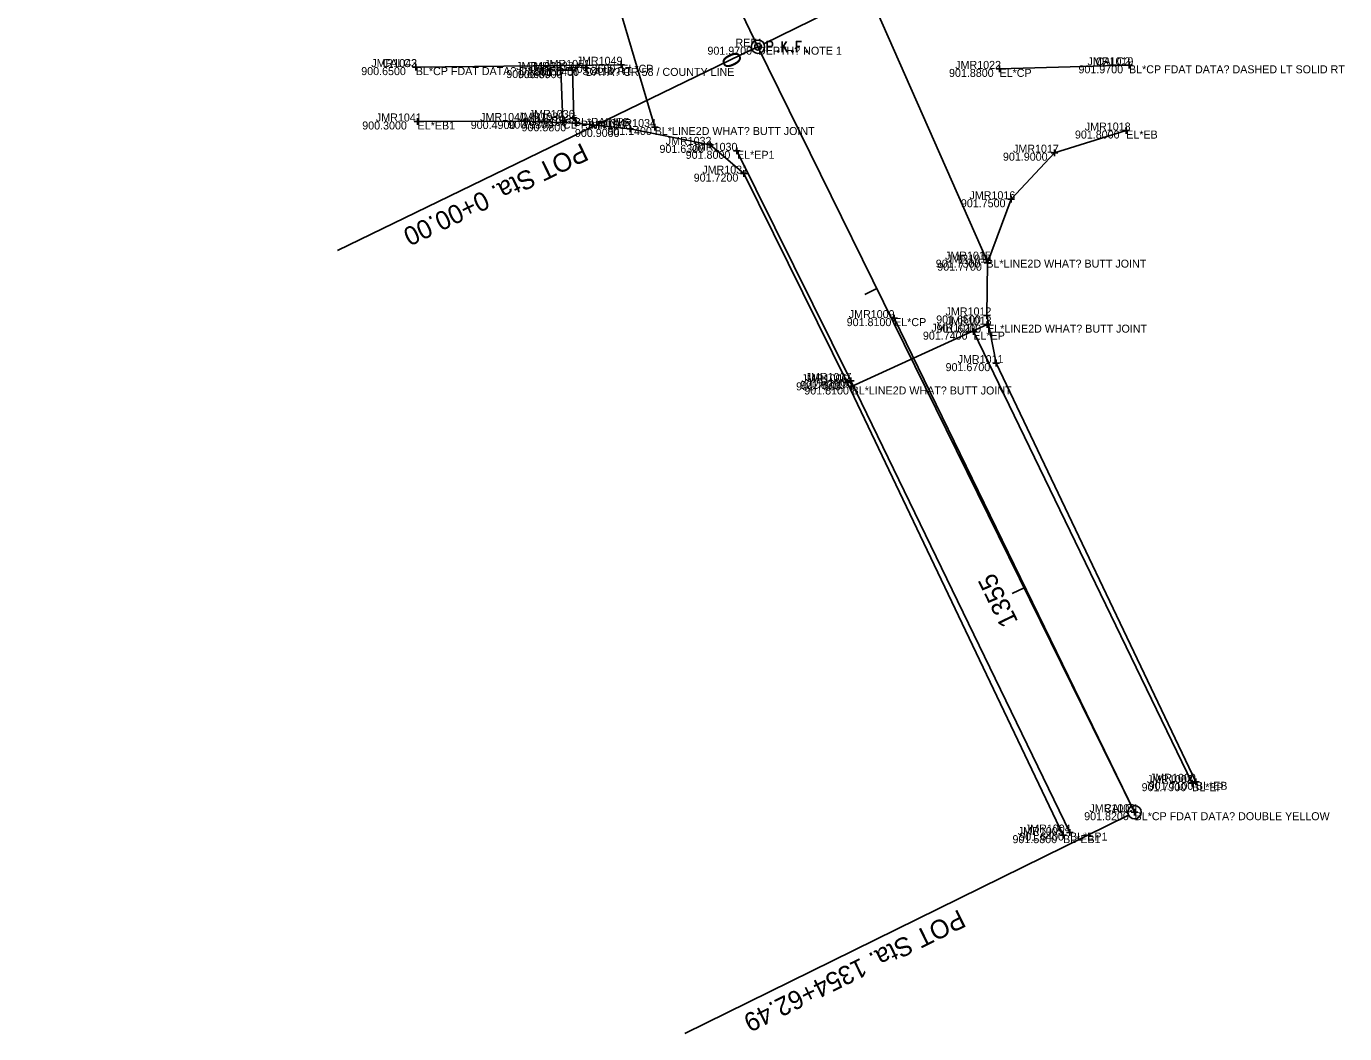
# Model space of a CAD drawing. Extents: x 1800057 to 1804439, y 483822 to 495007.
# Drawn here: x 1804241.5 to 1804439.2, y 483821.7 to 483972.7 of the extents above; entities that cross this region are included whole.
import ezdxf

# ---------------------------------------------------------------- set-up
doc = ezdxf.new("R2010")
doc.units = 0
for name, color, linetype in [('Default', 7, 'Continuous'), ('PM_X_Stop_Line', 7, 'Continuous'), ('PV_X_EOP', 7, 'Continuous'), ('PV_X_Shoulder', 7, 'Continuous'), ('SV_X_Center_of_Pavt', 7, 'Continuous'), ('SV_X_CL_Survey_20', 7, 'Continuous'), ('SV_X_Control_Cells_Found', 7, 'Continuous'), ('SV_X_Shot_Marker', 7, 'Continuous'), ('SV_X_Text_Comment', 7, 'Continuous'), ('SV_X_Text_Elevation', 7, 'Continuous'), ('SV_X_Text_Name', 7, 'Continuous')]:
    doc.layers.add(name, color=color, linetype=linetype)

msp = doc.modelspace()

# ---------------------------------------------------------------- linework, layer by layer
at = {"layer": 'Default'}
for p, q in [((1804335.76, 483957.63), (1804326.1, 483990.39)), ((1804385.49, 483937.75), (1804367.66, 483978.25)), ((1804365.29, 483918.73), (1804385.6, 483928))]:
    msp.add_line(p, q, dxfattribs=at)
at = {"layer": 'PM_X_Stop_Line'}
msp.add_lwpolyline([(1804323.65, 483958.99), (1804323.43, 483966.15), (1804321.7, 483966.17), (1804322, 483958.59), (1804323.65, 483958.99)], dxfattribs=at)
at = {"layer": 'PV_X_EOP'}
msp.add_line((1804416.35, 483859.26), (1804383.54, 483926.95), dxfattribs=at)
msp.add_lwpolyline([(1804398.03, 483851.86), (1804365.17, 483919.56), (1804348.1, 483954.06)], dxfattribs=at)
at = {"layer": 'PV_X_Shoulder'}
for points in [[(1804396.99, 483851.47), (1804364.63, 483919.35), (1804349.15, 483950.64), (1804344.09, 483954.95), (1804332.09, 483957.34), (1804323.97, 483958.19), (1804316.38, 483958.53), (1804300.21, 483958.46)], [(1804416.91, 483859.47), (1804386.95, 483922.23), (1804385.56, 483929.38), (1804385.67, 483937.29), (1804389.23, 483946.8), (1804395.69, 483953.78), (1804406.46, 483957.1)]]:
    msp.add_lwpolyline(points, dxfattribs=at)
at = {"layer": 'SV_X_Center_of_Pavt'}
for p, q in [((1804299.94, 483966.61), (1804330.75, 483966.96)), ((1804406.88, 483966.88), (1804387.46, 483966.34)), ((1804407.72, 483854.91), (1804371.66, 483928.98))]:
    msp.add_line(p, q, dxfattribs=at)
at = {"layer": 'SV_X_CL_Survey_20'}
for p, q in [((1804351.25, 483969.67), (1804113.2, 484460.86)), ((1804352.15, 483970.11), (1804419.84, 484003.42)), ((1804351.25, 483969.67), (1804349.45, 483968.8)), ((1804407.72, 483854.91), (1804351.25, 483969.67)), ((1804350.35, 483969.23), (1804288.18, 483939.1)), ((1804369.08, 483933.43), (1804367.29, 483932.54)), ((1804391.16, 483888.56), (1804389.36, 483887.68)), ((1804406.82, 483854.46), (1804340.26, 483821.71))]:
    msp.add_line(p, q, dxfattribs=at)
for centre in [(1804351.25, 483969.67), (1804351.25, 483969.67), (1804407.72, 483854.91)]:
    msp.add_circle(centre, 1, dxfattribs=at)
at = {"layer": 'SV_X_Control_Cells_Found'}
for points in [[(1804352.61, 483968.87), (1804352.61, 483970.47), (1804353.14, 483970.47), (1804353.19, 483970.46), (1804353.27, 483970.43), (1804353.3, 483970.41), (1804353.34, 483970.38), (1804353.38, 483970.32), (1804353.41, 483970.26), (1804353.44, 483970.16), (1804353.44, 483970), (1804353.43, 483969.95), (1804353.4, 483969.88), (1804353.36, 483969.79), (1804353.32, 483969.75), (1804353.28, 483969.73), (1804353.23, 483969.7), (1804353.14, 483969.69), (1804352.61, 483969.69)], [(1804354.86, 483970.47), (1804354.86, 483968.87)], [(1804355.5, 483970.47), (1804354.86, 483969.45)], [(1804355.07, 483969.78), (1804355.61, 483968.87)], [(1804357.76, 483970.47), (1804357, 483970.47), (1804357, 483968.87)], [(1804357, 483969.69), (1804357.54, 483969.69)], [(1804354.25, 483969.08), (1804354.31, 483969.08), (1804354.34, 483969.06), (1804354.37, 483969.01), (1804354.37, 483968.95), (1804354.34, 483968.9), (1804354.31, 483968.87), (1804354.25, 483968.87), (1804354.22, 483968.9), (1804354.19, 483968.95), (1804354.19, 483969.01), (1804354.22, 483969.06), (1804354.25, 483969.08)], [(1804356.39, 483969.08), (1804356.45, 483969.08), (1804356.48, 483969.06), (1804356.51, 483969.01), (1804356.51, 483968.95), (1804356.48, 483968.9), (1804356.45, 483968.87), (1804356.39, 483968.87), (1804356.36, 483968.9), (1804356.32, 483968.95), (1804356.32, 483969.01), (1804356.36, 483969.06), (1804356.39, 483969.08)], [(1804358.54, 483969.08), (1804358.6, 483969.08), (1804358.63, 483969.06), (1804358.66, 483969.01), (1804358.66, 483968.95), (1804358.63, 483968.9), (1804358.6, 483968.87), (1804358.54, 483968.87), (1804358.51, 483968.9), (1804358.47, 483968.95), (1804358.47, 483969.01), (1804358.51, 483969.06), (1804358.54, 483969.08)]]:
    msp.add_lwpolyline(points, dxfattribs=at)
msp.add_circle((1804351.25, 483969.67), 0.497, dxfattribs=at)
at = {"layer": 'SV_X_Shot_Marker'}
for p, q in [((1804299.44, 483966.61), (1804300.44, 483966.61)), ((1804299.44, 483966.61), (1804300.44, 483966.61)), ((1804299.94, 483967.11), (1804299.94, 483966.11)), ((1804299.94, 483967.11), (1804299.94, 483966.11)), ((1804299.94, 483966.61), (1804299.94, 483966.61)), ((1804299.94, 483966.61), (1804299.94, 483966.61)), ((1804321.2, 483966.17), (1804322.2, 483966.17)), ((1804321.7, 483966.67), (1804321.7, 483965.67)), ((1804321.7, 483966.17), (1804321.7, 483966.17)), ((1804322.93, 483966.15), (1804323.93, 483966.15)), ((1804323.43, 483966.65), (1804323.43, 483965.65)), ((1804323.43, 483966.15), (1804323.43, 483966.15)), ((1804324.92, 483966.49), (1804325.92, 483966.49)), ((1804325.42, 483966.99), (1804325.42, 483965.99)), ((1804325.42, 483966.49), (1804325.42, 483966.49)), ((1804330.25, 483966.96), (1804331.25, 483966.96)), ((1804330.75, 483967.46), (1804330.75, 483966.46)), ((1804330.75, 483966.96), (1804330.75, 483966.96)), ((1804386.96, 483966.34), (1804387.96, 483966.34)), ((1804387.46, 483966.84), (1804387.46, 483965.84)), ((1804387.46, 483966.34), (1804387.46, 483966.34)), ((1804406.38, 483966.88), (1804407.38, 483966.88)), ((1804406.38, 483966.88), (1804407.38, 483966.88)), ((1804406.88, 483967.38), (1804406.88, 483966.38)), ((1804406.88, 483967.38), (1804406.88, 483966.38)), ((1804406.88, 483966.88), (1804406.88, 483966.88)), ((1804406.88, 483966.88), (1804406.88, 483966.88)), ((1804299.71, 483958.46), (1804300.71, 483958.46)), ((1804300.21, 483958.96), (1804300.21, 483957.96)), ((1804300.21, 483958.46), (1804300.21, 483958.46)), ((1804315.88, 483958.53), (1804316.88, 483958.53)), ((1804316.38, 483959.03), (1804316.38, 483958.03)), ((1804316.38, 483958.53), (1804316.38, 483958.53)), ((1804321.5, 483958.59), (1804322.5, 483958.59)), ((1804322, 483959.09), (1804322, 483958.09)), ((1804322, 483958.59), (1804322, 483958.59)), ((1804323.15, 483958.99), (1804324.15, 483958.99)), ((1804323.47, 483958.19), (1804324.47, 483958.19)), ((1804323.65, 483959.49), (1804323.65, 483958.49)), ((1804323.65, 483958.99), (1804323.65, 483958.99)), ((1804323.97, 483958.69), (1804323.97, 483957.69)), ((1804323.97, 483958.19), (1804323.97, 483958.19)), ((1804332.09, 483957.84), (1804332.09, 483956.84)), ((1804335.76, 483958.13), (1804335.76, 483957.13)), ((1804331.59, 483957.34), (1804332.59, 483957.34)), ((1804332.09, 483957.34), (1804332.09, 483957.34)), ((1804335.26, 483957.63), (1804336.26, 483957.63)), ((1804335.76, 483957.63), (1804335.76, 483957.63)), ((1804405.96, 483957.1), (1804406.96, 483957.1)), ((1804406.46, 483957.6), (1804406.46, 483956.6)), ((1804406.46, 483957.1), (1804406.46, 483957.1)), ((1804343.59, 483954.95), (1804344.59, 483954.95)), ((1804344.09, 483955.45), (1804344.09, 483954.45)), ((1804344.09, 483954.95), (1804344.09, 483954.95)), ((1804347.6, 483954.06), (1804348.6, 483954.06)), ((1804348.1, 483954.56), (1804348.1, 483953.56)), ((1804348.1, 483954.06), (1804348.1, 483954.06)), ((1804395.19, 483953.78), (1804396.19, 483953.78)), ((1804395.69, 483954.28), (1804395.69, 483953.28)), ((1804395.69, 483953.78), (1804395.69, 483953.78)), ((1804348.65, 483950.64), (1804349.65, 483950.64)), ((1804349.15, 483951.14), (1804349.15, 483950.14)), ((1804349.15, 483950.64), (1804349.15, 483950.64)), ((1804388.73, 483946.8), (1804389.73, 483946.8)), ((1804389.23, 483947.3), (1804389.23, 483946.3)), ((1804389.23, 483946.8), (1804389.23, 483946.8)), ((1804385.49, 483938.25), (1804385.49, 483937.25)), ((1804384.99, 483937.75), (1804385.99, 483937.75)), ((1804385.17, 483937.29), (1804386.17, 483937.29)), ((1804385.49, 483937.75), (1804385.49, 483937.75)), ((1804385.67, 483937.79), (1804385.67, 483936.79)), ((1804385.67, 483937.29), (1804385.67, 483937.29)), ((1804371.16, 483928.98), (1804372.16, 483928.98)), ((1804371.66, 483929.48), (1804371.66, 483928.48)), ((1804371.66, 483928.98), (1804371.66, 483928.98)), ((1804385.06, 483929.38), (1804386.06, 483929.38)), ((1804385.56, 483929.88), (1804385.56, 483928.88)), ((1804385.56, 483929.38), (1804385.56, 483929.38)), ((1804385.6, 483928.5), (1804385.6, 483927.5)), ((1804383.04, 483926.95), (1804384.04, 483926.95)), ((1804383.54, 483927.45), (1804383.54, 483926.45)), ((1804383.54, 483926.95), (1804383.54, 483926.95)), ((1804385.1, 483928), (1804386.1, 483928)), ((1804385.6, 483928), (1804385.6, 483928)), ((1804386.45, 483922.23), (1804387.45, 483922.23)), ((1804386.95, 483922.73), (1804386.95, 483921.73)), ((1804386.95, 483922.23), (1804386.95, 483922.23)), ((1804364.13, 483919.35), (1804365.13, 483919.35)), ((1804364.63, 483919.85), (1804364.63, 483918.85)), ((1804364.63, 483919.35), (1804364.63, 483919.35)), ((1804364.67, 483919.56), (1804365.67, 483919.56)), ((1804364.79, 483918.73), (1804365.79, 483918.73)), ((1804365.17, 483920.06), (1804365.17, 483919.06)), ((1804365.17, 483919.56), (1804365.17, 483919.56)), ((1804365.29, 483919.23), (1804365.29, 483918.23)), ((1804365.29, 483918.73), (1804365.29, 483918.73)), ((1804415.85, 483859.26), (1804416.85, 483859.26)), ((1804416.35, 483859.76), (1804416.35, 483858.76)), ((1804416.35, 483859.26), (1804416.35, 483859.26)), ((1804416.41, 483859.47), (1804417.41, 483859.47)), ((1804416.91, 483859.97), (1804416.91, 483858.97)), ((1804416.91, 483859.47), (1804416.91, 483859.47)), ((1804407.22, 483854.91), (1804408.22, 483854.91)), ((1804407.22, 483854.91), (1804408.22, 483854.91)), ((1804407.72, 483855.41), (1804407.72, 483854.41)), ((1804407.72, 483855.41), (1804407.72, 483854.41)), ((1804407.72, 483854.91), (1804407.72, 483854.91)), ((1804407.72, 483854.91), (1804407.72, 483854.91)), ((1804396.49, 483851.47), (1804397.49, 483851.47)), ((1804396.99, 483851.97), (1804396.99, 483850.97)), ((1804396.99, 483851.47), (1804396.99, 483851.47)), ((1804397.53, 483851.86), (1804398.53, 483851.86)), ((1804398.03, 483852.36), (1804398.03, 483851.36)), ((1804398.03, 483851.86), (1804398.03, 483851.86))]:
    msp.add_line(p, q, dxfattribs=at)

# ---------------------------------------------------------------- texts
at = {"layer": 'SV_X_CL_Survey_20'}
for s, rotation, p in [('0', 115.8566, (1804349.03, 483967.36)), ('POT Sta. 0+00.00', 205.8566, (1804324.86, 483955.33)), ('1355', 116.1993, (1804390.31, 483883.49)), ('POT Sta. 1354+62.49', 206.1993, (1804381.42, 483840.4))]:
    msp.add_text(s, height=2.8, rotation=rotation, dxfattribs=at).set_placement(p)
at = {"layer": 'SV_X_Text_Comment'}
for s, p in [('DEPTH? NOTE 1', (1804351.25, 483968.47)), ('BL*CP FDAT DATA? DASHED LT SOLID RT', (1804299.94, 483965.41)), ('DATA? CR 58 / COUNTY LINE', (1804325.42, 483965.29)), ('EL*CP', (1804330.75, 483965.76)), ('EL*CP', (1804387.46, 483965.14)), ('BL*CP FDAT DATA? DASHED LT SOLID RT', (1804406.88, 483965.68)), ('EL*EB1', (1804300.21, 483957.26)), ('CL*PAINTS', (1804322, 483957.39)), ('BL*PAINTS', (1804323.65, 483957.79)), ('BL*LINE2D WHAT? BUTT JOINT', (1804335.76, 483956.43)), ('EL*EB', (1804406.46, 483955.9)), ('EL*EP1', (1804348.1, 483952.86)), ('BL*LINE2D WHAT? BUTT JOINT', (1804385.49, 483936.55)), ('EL*CP', (1804371.66, 483927.78)), ('EL*EP', (1804383.54, 483925.75)), ('EL*LINE2D WHAT? BUTT JOINT', (1804385.6, 483926.8)), ('BL*LINE2D WHAT? BUTT JOINT', (1804365.29, 483917.53)), ('BL*EP', (1804416.35, 483858.06)), ('BL*EB', (1804416.91, 483858.27)), ('BL*CP FDAT DATA? DOUBLE YELLOW', (1804407.72, 483853.71)), ('BL*EB1', (1804396.99, 483850.27)), ('BL*EP1', (1804398.03, 483850.66))]:
    msp.add_text(s, height=1.2, dxfattribs=at).set_placement(p)
at = {"layer": 'SV_X_Text_Elevation'}
for s, p in [('901.9700', (1804343.67, 483968.47)), ('900.6500', (1804291.76, 483965.41)), ('900.6500', (1804291.76, 483965.41)), ('900.8600', (1804313.51, 483964.97)), ('900.8900', (1804315.24, 483964.95)), ('901.0400', (1804317.72, 483965.29)), ('901.2600', (1804323.17, 483965.76)), ('901.8800', (1804379.89, 483965.14)), ('901.9700', (1804399.3, 483965.68)), ('901.9700', (1804399.3, 483965.68)), ('900.3000', (1804291.91, 483957.26)), ('900.4900', (1804308.18, 483957.33)), ('900.5300', (1804313.82, 483957.39)), ('900.5800', (1804315.8, 483956.99)), ('900.6100', (1804315.94, 483957.79)), ('900.9000', (1804323.8, 483956.14)), ('901.1400', (1804328.65, 483956.43)), ('901.8000', (1804398.77, 483955.9)), ('901.6300', (1804336.48, 483953.75)), ('901.8000', (1804340.41, 483952.86)), ('901.9000', (1804387.98, 483952.58)), ('901.7200', (1804341.61, 483949.44)), ('901.7500', (1804381.67, 483945.6)), ('901.7300', (1804377.91, 483936.55)), ('901.7700', (1804378.13, 483936.09)), ('901.8100', (1804364.55, 483927.78)), ('901.6500', (1804377.97, 483928.18)), ('901.7400', (1804375.98, 483925.75)), ('901.6200', (1804378.02, 483926.8)), ('901.6700', (1804379.38, 483921.03)), ('901.7000', (1804356.96, 483918.15)), ('901.8300', (1804357.57, 483918.36)), ('901.8100', (1804358.19, 483917.53)), ('901.7900', (1804408.77, 483858.06)), ('901.7100', (1804409.83, 483858.27)), ('901.8200', (1804400.16, 483853.71)), ('901.8200', (1804400.16, 483853.71)), ('901.5800', (1804389.41, 483850.27)), ('901.6400', (1804390.43, 483850.66))]:
    msp.add_text(s, height=1.2, dxfattribs=at).set_placement(p)
at = {"layer": 'SV_X_Text_Name'}
for s, p in [('REF1', (1804347.87, 483969.67)), ('JMR1042', (1804293.27, 483966.61)), ('CALC3', (1804294.94, 483966.61)), ('JMR1051', (1804319.19, 483966.49)), ('JMR1049', (1804324.06, 483966.96)), ('JMR1019', (1804400.67, 483966.88)), ('CALC2', (1804401.89, 483966.88)), ('JMR1038', (1804315, 483966.17)), ('JMR1037', (1804316.74, 483966.15)), ('JMR1022', (1804380.82, 483966.34)), ('JMR1041', (1804293.96, 483958.46)), ('JMR1040', (1804309.59, 483958.53)), ('JMR1039', (1804315.31, 483958.59)), ('JMR1036', (1804316.88, 483958.99)), ('JMR1035', (1804317.28, 483958.19)), ('JMR1033', (1804325.4, 483957.34)), ('JMR1034', (1804329.08, 483957.63)), ('JMR1018', (1804400.25, 483957.1)), ('JMR1032', (1804337.41, 483954.95)), ('JMR1030', (1804341.3, 483954.06)), ('JMR1017', (1804389.49, 483953.78)), ('JMR1031', (1804342.9, 483950.64)), ('JMR1016', (1804382.96, 483946.8)), ('JMR1015', (1804379.29, 483937.75)), ('JMR1014', (1804379.48, 483937.29)), ('JMR1009', (1804364.86, 483928.98)), ('JMR1012', (1804379.38, 483929.38)), ('JMR1010', (1804377.24, 483926.95)), ('JMR1013', (1804379.4, 483928)), ('JMR1011', (1804381.19, 483922.23)), ('JMR1006', (1804357.78, 483919.35)), ('JMR1007', (1804358.39, 483919.56)), ('JMR1008', (1804358.5, 483918.73)), ('JMR1002', (1804409.57, 483859.26)), ('JMR1000', (1804410.03, 483859.47)), ('JMR1003', (1804400.94, 483854.91)), ('CALC1', (1804403.15, 483854.91)), ('JMR1004', (1804391.26, 483851.86)), ('JMR1005', (1804390.21, 483851.47))]:
    msp.add_text(s, height=1.2, dxfattribs=at).set_placement(p)

doc.saveas('drawing.dxf')
